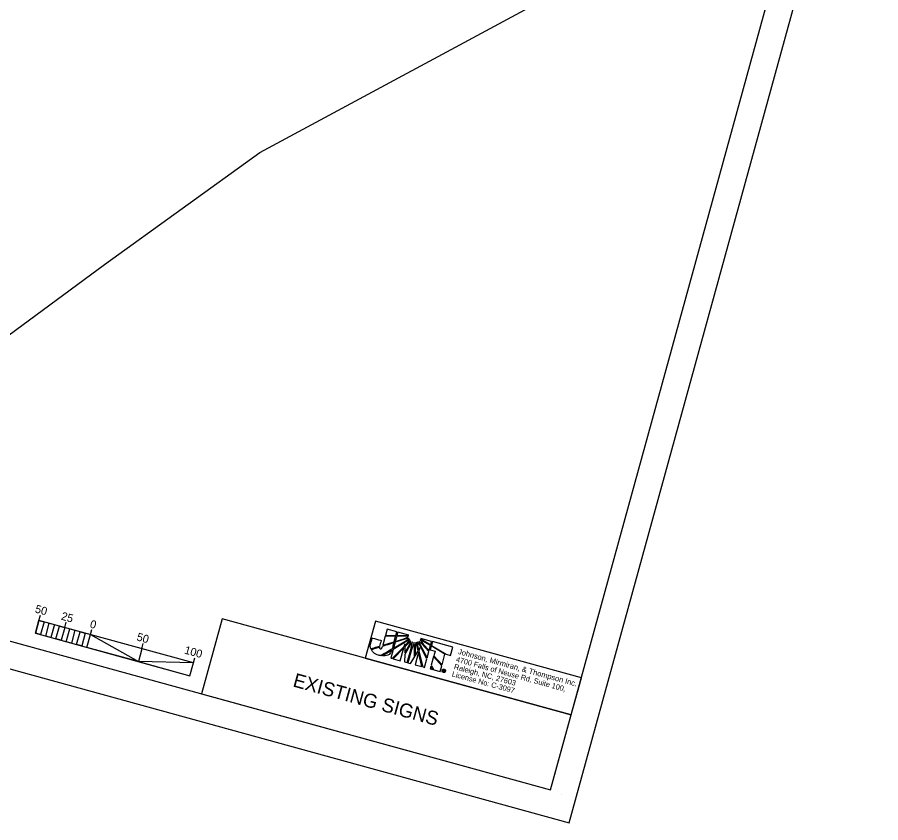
# Model space of a CAD drawing. Extents: x 1641195 to 1643343, y 841291 to 842800.
# Drawn here: x 1642306 to 1643114, y 841291 to 842045 of the extents above; entities that cross this region are included whole.
import ezdxf

# ---------------------------------------------------------------- set-up
doc = ezdxf.new("R2010")
doc.units = 0
for name, color, linetype in [('Default', 7, 'Continuous'), ('Level 18', 7, 'Continuous'), ('Level 2', 7, 'Continuous'), ('Level 20', 7, 'Continuous'), ('Level 3', 7, 'Continuous'), ('Level 6', 7, 'Continuous')]:
    doc.layers.add(name, color=color, linetype=linetype)

msp = doc.modelspace()

# ---------------------------------------------------------------- linework, layer by layer
at = {"layer": 'Default'}
for p, q in [((1642652.16, 841471.93), (1642650.52, 841465.95)), ((1642661.19, 841469.46), (1642652.16, 841471.93)), ((1642650.33, 841465.26), (1642648.02, 841456.84)), ((1642660.05, 841465.32), (1642650.33, 841465.26)), ((1642650.52, 841465.95), (1642660.23, 841465.97)), ((1642658.62, 841460.09), (1642660.05, 841465.32)), ((1642661.06, 841465.31), (1642659.72, 841460.43)), ((1642660.23, 841465.97), (1642661.19, 841469.46)), ((1642669.2, 841465.32), (1642661.06, 841465.31)), ((1642662.14, 841469.25), (1642661.25, 841466.01)), ((1642661.25, 841466.01), (1642669.39, 841466.02)), ((1642672.3, 841466.46), (1642662.14, 841469.25)), ((1642667.67, 841462.86), (1642672.25, 841464.87)), ((1642672.61, 841463.27), (1642668.69, 841462.47)), ((1642672.25, 841464.87), (1642669.2, 841465.32)), ((1642669.39, 841466.02), (1642672.3, 841466.46)), ((1642670.19, 841461.3), (1642672.61, 841463.27)), ((1642693.8, 841460.52), (1642683.8, 841463.31)), ((1642683.8, 841463.31), (1642686, 841461.42)), ((1642648.02, 841456.84), (1642658.62, 841460.09)), ((1642656.94, 841444.45), (1642667.97, 841455.76)), ((1642670.45, 841460.71), (1642657.7, 841453.05)), ((1642657.96, 841454.01), (1642670.19, 841461.3)), ((1642659.5, 841459.64), (1642657.96, 841454.01)), ((1642668.69, 841462.47), (1642659.5, 841459.64)), ((1642659.72, 841460.43), (1642667.67, 841462.86)), ((1642667.97, 841455.76), (1642668.62, 841458.15)), ((1642673.78, 841457.37), (1642668.55, 841448.31)), ((1642668.6, 841449.65), (1642673.41, 841458.02)), ((1642668.64, 841455.47), (1642668.6, 841449.65)), ((1642668.62, 841456.38), (1642671.46, 841459.31)), ((1642668.62, 841458.15), (1642668.62, 841456.38)), ((1642672.01, 841458.93), (1642668.64, 841455.47)), ((1642673.35, 841461.9), (1642670.45, 841460.71)), ((1642671.46, 841459.31), (1642673.35, 841461.9)), ((1642674.43, 841460.74), (1642672.01, 841458.93)), ((1642673.41, 841458.02), (1642674.43, 841460.74)), ((1642675.81, 841459.92), (1642673.78, 841457.37)), ((1642674.24, 841452.7), (1642675.81, 841459.92)), ((1642677.3, 841459.52), (1642674.88, 841452.52)), ((1642677.7, 841456.3), (1642677.3, 841459.52)), ((1642677.57, 841445.68), (1642677.7, 841456.3)), ((1642678.36, 841456.55), (1642678.2, 841446.79)), ((1642678.85, 841459.52), (1642678.36, 841456.55)), ((1642679.97, 841456.75), (1642678.85, 841459.52)), ((1642681.14, 841451.88), (1642679.97, 841456.75)), ((1642680.35, 841459.98), (1642680.66, 841456.78)), ((1642682.25, 841457.47), (1642680.35, 841459.98)), ((1642680.66, 841456.78), (1642681.62, 841452.66)), ((1642681.71, 841460.77), (1642682.77, 841457.81)), ((1642684.72, 841458.07), (1642681.71, 841460.77)), ((1642689.28, 841444.3), (1642682.25, 841457.47)), ((1642682.77, 841457.81), (1642689.54, 841445.23)), ((1642682.88, 841461.96), (1642685.82, 841457.82)), ((1642685.57, 841460.84), (1642682.88, 841461.96)), ((1642691.13, 841451.02), (1642684.72, 841458.07)), ((1642692.72, 841456.59), (1642685.57, 841460.84)), ((1642685.82, 841457.82), (1642691.35, 841451.82)), ((1642686, 841461.42), (1642692.91, 841457.27)), ((1642691.35, 841451.82), (1642692.72, 841456.59)), ((1642693.36, 841456.19), (1642692.36, 841452.55)), ((1642692.91, 841457.27), (1642693.8, 841460.52)), ((1642693.38, 841456.24), (1642693.36, 841456.19)), ((1642706.27, 841448.42), (1642693.38, 841456.24)), ((1642693.55, 841456.89), (1642693.52, 841456.78)), ((1642693.52, 841456.78), (1642707.32, 841448.5)), ((1642694.51, 841460.37), (1642693.55, 841456.89)), ((1642713.49, 841455.17), (1642694.51, 841460.37)), ((1642711.36, 841447.39), (1642713.49, 841455.17)), ((1642657.7, 841453.05), (1642655.45, 841444.86)), ((1642667.61, 841454.47), (1642657.64, 841444.26)), ((1642664.37, 841442.41), (1642667.61, 841454.47)), ((1642668.55, 841448.31), (1642668.47, 841441.34)), ((1642670.94, 841440.66), (1642674.24, 841452.7)), ((1642674.88, 841452.52), (1642671.58, 841440.48)), ((1642678.2, 841446.79), (1642681.14, 841451.88)), ((1642681.49, 841450.39), (1642678.27, 841438.65)), ((1642684.74, 841436.88), (1642681.49, 841450.39)), ((1642681.62, 841452.66), (1642682.57, 841454.32)), ((1642682.57, 841454.32), (1642681.84, 841451.69)), ((1642681.84, 841451.69), (1642685.47, 841436.63)), ((1642689.54, 841445.23), (1642691.13, 841451.02)), ((1642692.36, 841452.55), (1642697, 841451.28)), ((1642697, 841451.28), (1642695.81, 841446.94)), ((1642695.81, 841446.94), (1642703.54, 841438.45)), ((1642703.54, 841438.45), (1642706.27, 841448.42)), ((1642707.32, 841448.5), (1642711.36, 841447.39)), ((1642655.45, 841444.86), (1642656.94, 841444.45)), ((1642657.64, 841444.26), (1642664.37, 841442.41)), ((1642668.47, 841441.34), (1642670.94, 841440.66)), ((1642671.58, 841440.48), (1642674.08, 841439.8)), ((1642674.08, 841439.8), (1642677.57, 841445.68)), ((1642678.27, 841438.65), (1642684.74, 841436.88)), ((1642687.06, 841436.19), (1642689.28, 841444.3)), ((1642695.6, 841446.2), (1642693.39, 841438.12)), ((1642703.35, 841437.75), (1642695.6, 841446.2)), ((1642685.47, 841436.63), (1642687.06, 841436.19)), ((1642693.15, 841437.25), (1642692.46, 841434.71)), ((1642692.46, 841434.71), (1642694.79, 841434.07)), ((1642694.79, 841434.07), (1642693.15, 841437.25)), ((1642693.39, 841438.12), (1642695.69, 841433.83)), ((1642695.69, 841433.83), (1642701.81, 841432.15)), ((1642701.81, 841432.15), (1642703.35, 841437.75)), ((1642704.42, 841432.35), (1642704.8, 841433.73)), ((1642704.74, 841432.26), (1642704.42, 841432.35)), ((1642704.88, 841432.8), (1642704.74, 841432.26)), ((1642704.84, 841431.65), (1642704.76, 841431.35)), ((1642704.76, 841431.35), (1642704.84, 841431.65)), ((1642704.77, 841431.35), (1642704.76, 841431.35)), ((1642704.8, 841433.73), (1642705.37, 841433.57)), ((1642704.84, 841431.65), (1642704.85, 841431.65)), ((1642705.13, 841432.73), (1642704.88, 841432.8)), ((1642705.04, 841433.38), (1642704.95, 841433.05)), ((1642704.95, 841433.05), (1642705.2, 841432.98)), ((1642705.29, 841433.31), (1642705.04, 841433.38)), ((1642705.2, 841432.98), (1642705.13, 841432.73)), ((1642705.13, 841432.73), (1642705.2, 841432.98)), ((1642705.15, 841432.73), (1642705.13, 841432.73)), ((1642705.2, 841432.98), (1642705.22, 841432.98)), ((1642705.37, 841433.57), (1642705.29, 841433.31)), ((1642705.29, 841433.31), (1642705.37, 841433.57)), ((1642705.33, 841433.3), (1642705.29, 841433.31)), ((1642705.37, 841433.57), (1642705.45, 841433.55)), ((1642705.59, 841434.39), (1642705.51, 841434.1)), ((1642705.51, 841434.1), (1642705.59, 841434.39))]:
    msp.add_line(p, q, dxfattribs=at)
msp.add_lwpolyline([(1642631.55, 841444.76), (1642824.42, 841391.68), (1642833.99, 841426.49), (1642641.13, 841479.56)], close=True, dxfattribs=at)
for points in [[(1642650.52, 841465.95), (1642660.23, 841465.97), (1642661.19, 841469.46), (1642652.16, 841471.93), (1642650.52, 841465.95)], [(1642648.02, 841456.84), (1642658.62, 841460.09), (1642660.05, 841465.32), (1642650.33, 841465.26), (1642648.02, 841456.84)], [(1642659.5, 841459.64), (1642657.96, 841454.01), (1642670.19, 841461.3), (1642672.61, 841463.27), (1642668.69, 841462.47), (1642659.5, 841459.64)], [(1642661.06, 841465.31), (1642659.72, 841460.43), (1642667.67, 841462.86), (1642672.25, 841464.87), (1642669.2, 841465.32), (1642661.06, 841465.31)], [(1642669.39, 841466.02), (1642672.3, 841466.46), (1642662.14, 841469.25), (1642661.25, 841466.01), (1642669.39, 841466.02)], [(1642686, 841461.42), (1642692.91, 841457.27), (1642693.8, 841460.52), (1642683.8, 841463.31), (1642686, 841461.42)], [(1642673.35, 841461.9), (1642670.45, 841460.71), (1642657.7, 841453.05), (1642655.45, 841444.86), (1642656.94, 841444.45), (1642667.97, 841455.76), (1642668.62, 841458.15), (1642668.62, 841456.38), (1642671.46, 841459.31), (1642673.35, 841461.9)], [(1642673.78, 841457.37), (1642668.55, 841448.31), (1642668.47, 841441.34), (1642670.94, 841440.66), (1642674.24, 841452.7), (1642675.81, 841459.92), (1642673.78, 841457.37)], [(1642674.43, 841460.74), (1642672.01, 841458.93), (1642668.64, 841455.47), (1642668.6, 841449.65), (1642673.41, 841458.02), (1642674.43, 841460.74)], [(1642677.3, 841459.52), (1642674.88, 841452.52), (1642671.58, 841440.48), (1642674.08, 841439.8), (1642677.57, 841445.68), (1642677.7, 841456.3), (1642677.3, 841459.52)], [(1642678.85, 841459.52), (1642678.36, 841456.55), (1642678.2, 841446.79), (1642681.14, 841451.88), (1642679.97, 841456.75), (1642678.85, 841459.52)], [(1642680.35, 841459.98), (1642680.66, 841456.78), (1642681.62, 841452.66), (1642682.57, 841454.32), (1642681.84, 841451.69), (1642685.47, 841436.63), (1642687.06, 841436.19), (1642689.28, 841444.3), (1642682.25, 841457.47), (1642680.35, 841459.98)], [(1642681.71, 841460.77), (1642682.77, 841457.81), (1642689.54, 841445.23), (1642691.13, 841451.02), (1642684.72, 841458.07), (1642681.71, 841460.77)], [(1642682.88, 841461.96), (1642685.82, 841457.82), (1642691.35, 841451.82), (1642692.72, 841456.59), (1642685.57, 841460.84), (1642682.88, 841461.96)], [(1642693.38, 841456.24), (1642693.36, 841456.19), (1642692.36, 841452.55), (1642697, 841451.28), (1642695.81, 841446.94), (1642703.54, 841438.45), (1642706.27, 841448.42), (1642693.38, 841456.24)], [(1642713.49, 841455.17), (1642694.51, 841460.37), (1642693.55, 841456.89), (1642693.52, 841456.78), (1642707.32, 841448.5), (1642711.36, 841447.39), (1642713.49, 841455.17)], [(1642657.64, 841444.26), (1642664.37, 841442.41), (1642667.61, 841454.47), (1642657.64, 841444.26)], [(1642678.27, 841438.65), (1642684.74, 841436.88), (1642681.49, 841450.39), (1642678.27, 841438.65)], [(1642695.6, 841446.2), (1642693.39, 841438.12), (1642695.69, 841433.83), (1642701.81, 841432.15), (1642703.35, 841437.75), (1642695.6, 841446.2), (1642695.6, 841446.2)], [(1642692.46, 841434.71), (1642692.46, 841434.71), (1642694.79, 841434.07), (1642693.15, 841437.25), (1642692.46, 841434.71)], [(1642705.68, 841432.35), (1642705.66, 841432.28), (1642705.66, 841432.23), (1642705.64, 841432.18), (1642705.64, 841432.02), (1642705.35, 841432.09)]]:
    msp.add_lwpolyline(points, dxfattribs=at)
for points, degree in [([(1642646.49, 841461.43), (1642646.49, 841461.43), (1642638.13, 841463.72), (1642638.13, 841463.72), (1642638.13, 841463.72), (1642636.7, 841458.49), (1642636.7, 841458.49), (1642636.7, 841458.49), (1642636.55, 841457.94), (1642636.55, 841457.94), (1642636.1, 841456.3), (1642636.28, 841454.86), (1642636.93, 841453.51), (1642636.93, 841453.51), (1642644.95, 841455.8), (1642644.97, 841455.9), (1642644.97, 841455.9), (1642646.49, 841461.43), (1642646.49, 841461.43)], 3), ([(1642645.72, 841453.55), (1642645.19, 841453.7), (1642644.81, 841454.12), (1642644.89, 841455.17), (1642644.89, 841455.17), (1642637.31, 841452.94), (1642637.31, 841452.94), (1642638.73, 841450.29), (1642641.57, 841448.17), (1642644.27, 841447.43), (1642644.97, 841447.24), (1642645.52, 841447.15), (1642646.31, 841447.09), (1642646.31, 841447.09), (1642656.75, 841453.27), (1642656.75, 841453.27), (1642656.75, 841453.27), (1642658.41, 841459.34), (1642658.41, 841459.34), (1642658.41, 841459.34), (1642647.81, 841456.08), (1642647.81, 841456.08), (1642647.19, 841453.8), (1642646.47, 841453.34), (1642645.72, 841453.55)], 3), ([(1642645.72, 841453.55), (1642645.19, 841453.7), (1642644.81, 841454.12), (1642644.89, 841455.17), (1642644.89, 841455.17), (1642637.31, 841452.94), (1642637.31, 841452.94), (1642638.73, 841450.29), (1642641.57, 841448.17), (1642644.27, 841447.43), (1642644.97, 841447.24), (1642645.52, 841447.15), (1642646.31, 841447.09), (1642646.31, 841447.09), (1642656.75, 841453.27), (1642656.75, 841453.27), (1642656.75, 841453.27), (1642658.41, 841459.34), (1642658.41, 841459.34), (1642658.41, 841459.34), (1642647.81, 841456.08), (1642647.81, 841456.08), (1642647.19, 841453.8), (1642646.47, 841453.34), (1642645.72, 841453.55)], 3), ([(1642656.48, 841452.31), (1642656.48, 841452.31), (1642647.46, 841446.98), (1642647.46, 841446.98), (1642651.14, 841446.89), (1642655.19, 841448.23), (1642656.48, 841452.31)], 3), ([(1642704.76, 841431.35), (1642704.34, 841431.47), (1642704.02, 841431.72), (1642703.8, 841432.1), (1642703.58, 841432.47), (1642703.53, 841432.88), (1642703.65, 841433.3), (1642703.76, 841433.73), (1642704.01, 841434.05), (1642704.39, 841434.25), (1642704.77, 841434.45), (1642705.16, 841434.51), (1642705.59, 841434.39)], 3), ([(1642705.51, 841434.1), (1642705.17, 841434.19), (1642704.85, 841434.16), (1642704.55, 841434), (1642704.25, 841433.83), (1642704.04, 841433.56), (1642703.95, 841433.22), (1642703.85, 841432.88), (1642703.9, 841432.55), (1642704.07, 841432.24), (1642704.24, 841431.94), (1642704.5, 841431.75), (1642704.84, 841431.65)], 3), ([(1642706.72, 841432.46), (1642706.6, 841432.03), (1642706.35, 841431.71), (1642705.98, 841431.49), (1642705.6, 841431.28), (1642705.2, 841431.23), (1642704.77, 841431.35)], 3), ([(1642704.85, 841431.65), (1642705.19, 841431.56), (1642705.51, 841431.59), (1642705.81, 841431.76), (1642706.12, 841431.94), (1642706.33, 841432.2), (1642706.42, 841432.54), (1642706.51, 841432.88), (1642706.47, 841433.22), (1642706.3, 841433.52), (1642706.12, 841433.81), (1642705.86, 841434), (1642705.51, 841434.1)], 3), ([(1642705.37, 841432.61), (1642705.34, 841432.65), (1642705.27, 841432.7), (1642705.15, 841432.73)], 2), ([(1642705.22, 841432.98), (1642705.42, 841432.93), (1642705.53, 841432.96), (1642705.57, 841433.07), (1642705.59, 841433.17), (1642705.52, 841433.25), (1642705.33, 841433.3)], 3), ([(1642705.35, 841432.09), (1642705.33, 841432.18), (1642705.33, 841432.26), (1642705.36, 841432.36), (1642705.39, 841432.49), (1642705.4, 841432.57), (1642705.37, 841432.61)], 3), ([(1642705.45, 841433.55), (1642705.8, 841433.45), (1642705.94, 841433.27), (1642705.87, 841432.99), (1642705.83, 841432.87), (1642705.75, 841432.78), (1642705.62, 841432.73)], 3), ([(1642705.59, 841434.39), (1642706.02, 841434.27), (1642706.34, 841434.02), (1642706.56, 841433.65), (1642706.79, 841433.29), (1642706.84, 841432.89), (1642706.72, 841432.46)], 3), ([(1642705.62, 841432.73), (1642705.7, 841432.66), (1642705.71, 841432.53), (1642705.68, 841432.35)], 2)]:
    msp.add_open_spline(points, degree=degree, dxfattribs=at)
at = {"layer": 'Level 18'}
for p, q in [((1642325.97, 841480.18), (1642322.65, 841468.13)), ((1642325.97, 841480.18), (1642327.29, 841484.99)), ((1642470.59, 841440.4), (1642325.97, 841480.18)), ((1642350.07, 841473.54), (1642351.4, 841478.37)), ((1642374.17, 841466.91), (1642375.5, 841471.73)), ((1642322.65, 841468.13), (1642467.27, 841428.33)), ((1642359.71, 841470.9), (1642356.4, 841458.85)), ((1642422.38, 841453.66), (1642423.71, 841458.47)), ((1642422.38, 841453.66), (1642419.07, 841441.61)), ((1642467.27, 841428.33), (1642470.59, 841440.4)), ((1642470.59, 841440.4), (1642471.92, 841445.22))]:
    msp.add_line(p, q, dxfattribs=at)
for points in [[(1642325.97, 841480.18), (1642330.79, 841478.86), (1642327.47, 841466.81), (1642322.65, 841468.13)], [(1642478.1, 841411.43), (1642805.09, 841321.44), (1642824.42, 841391.68), (1642497.43, 841481.67)], [(1642335.61, 841477.53), (1642340.42, 841476.19), (1642337.11, 841464.14), (1642332.3, 841465.46)], [(1642345.25, 841474.87), (1642350.07, 841473.54), (1642346.75, 841461.5), (1642341.93, 841462.83)], [(1642354.89, 841472.21), (1642359.71, 841470.9), (1642356.4, 841458.85), (1642351.57, 841460.17)], [(1642364.53, 841469.57), (1642369.35, 841468.25), (1642366.03, 841456.18), (1642361.22, 841457.52)], [(1642374.17, 841466.91), (1642419.07, 841441.61), (1642370.86, 841454.86)], [(1642470.59, 841440.4), (1642419.07, 841441.61), (1642467.27, 841428.33)]]:
    msp.add_lwpolyline(points, close=True, dxfattribs=at)
at = {"layer": 'Level 2'}
msp.add_lwpolyline([(1641195.06, 841738.58), (1642822.56, 841290.71), (1643114.42, 842351.28), (1641486.92, 842799.16)], close=True, dxfattribs=at)
at = {"layer": 'Level 20'}
for p, q in [((1642325.98, 841480.19), (1642327.3, 841485)), ((1642350.08, 841473.55), (1642351.41, 841478.37)), ((1642422.4, 841453.67), (1642423.72, 841458.48)), ((1642470.6, 841440.39), (1642471.93, 841445.23))]:
    msp.add_line(p, q, dxfattribs=at)
at = {"layer": 'Level 3'}
for p, q in [((1642815.39, 841316.99), (1642815.39, 841316.99)), ((1642822.54, 841290.68), (1642822.54, 841290.68))]:
    msp.add_line(p, q, dxfattribs=at)
msp.add_lwpolyline([(1643083.96, 842334.84), (1641638.42, 842732.64), (1641359.54, 841719.25), (1642805.09, 841321.44)], close=True, dxfattribs=at)
at = {"layer": 'Level 6'}
msp.add_lwpolyline([(1641792.98, 842690.11), (1641752.38, 842181.83), (1641755.46, 842119.79), (1641627.17, 841958.82), (1641586.62, 841880.3), (1641436.07, 841811.6), (1641408.39, 841755.09), (1641452.55, 841742.94), (1641576.94, 841708.71), (1641653.36, 841687.67), (1641800.35, 841636.49), (1641872.21, 841608.48), (1641936.45, 841597.66), (1642028.27, 841572.39), (1642158.19, 841597.22), (1642252.63, 841714.28), (1642387.32, 841813.32), (1642532.75, 841918.25), (1642817.65, 842071.9), (1642849.16, 842186.32), (1642903.68, 842384.45)], close=True, dxfattribs=at)

# ---------------------------------------------------------------- texts
at = {"layer": 'Default'}
for s, height, p in [('Johnson, Mirmiran, & Thompson Inc.', 5.1112, (1642718.1, 841448.79)), ('Raleigh, NC, 27603', 4.9652, (1642714.23, 841434.72)), ('4700 Falls of Neuse Rd, Suite 100, ', 4.9652, (1642716.11, 841441.56)), ('EXISTING SIGNS', 13, (1642563.05, 841418.46)), ('License No: C-3097', 4.9652, (1642712.34, 841427.88))]:
    msp.add_text(s, height=height, rotation=344.61341, dxfattribs=at).set_placement(p)
at = {"layer": 'Level 18'}
for s, p in [('50', (1642321.74, 841487.71)), ('25', (1642346.17, 841480.99)), ('0', (1642373.15, 841473.57)), ('50', (1642416.96, 841461.52)), ('100', (1642461.64, 841449.22))]:
    msp.add_text(s, height=7.5, rotation=344.61818, dxfattribs=at).set_placement(p)

doc.saveas('drawing.dxf')
